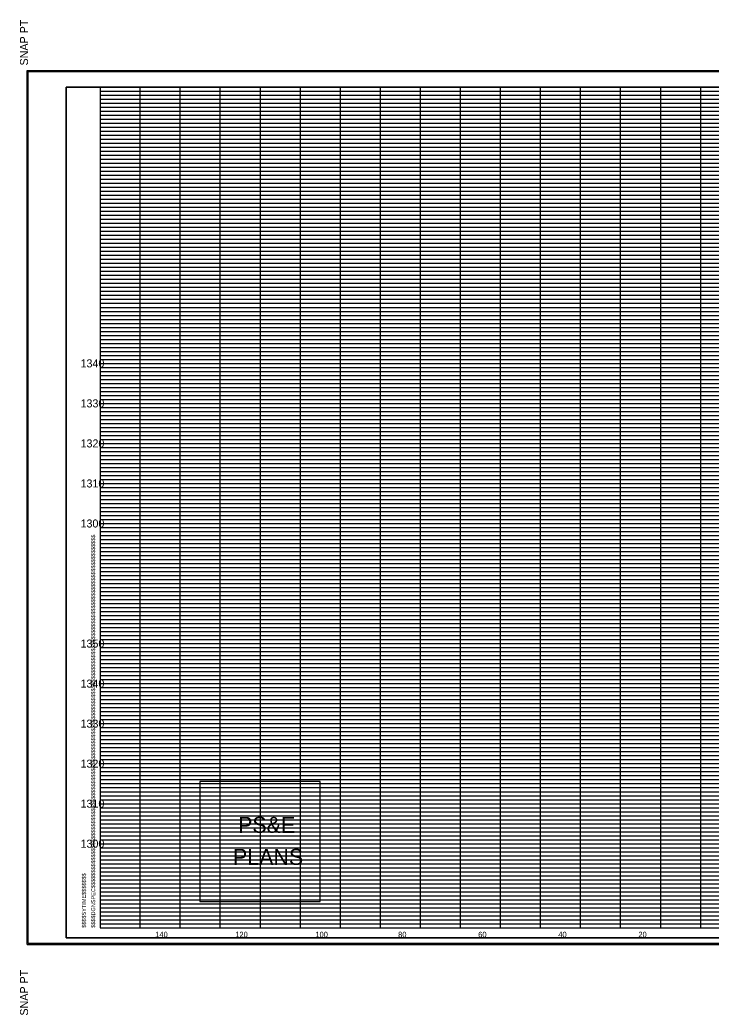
# Model space of a CAD drawing. Extents: x 980 to 1324, y 978 to 2847.
# Drawn here: x 979.9 to 1152.6, y 2328.2 to 2576.8 of the extents above; entities that cross this region are included whole.
import ezdxf

# ---------------------------------------------------------------- set-up
doc = ezdxf.new("R2010")
doc.units = 0
for name, color, linetype in [('DESIGN - SHEET - Corner Text', 7, 'Continuous'), ('DESIGN - SHEET - Light Grid', 7, 'Continuous'), ('DESIGN - SHEET - Linework', 7, 'Continuous'), ('DESIGN - SHEET - Plot Shape', 7, 'Continuous'), ('DESIGN - TYPICAL - Text', 7, 'Continuous')]:
    doc.layers.add(name, color=color, linetype=linetype)

# ---------------------------------------------------------------- blocks, each defined once
blk = doc.blocks.new('XSTSHT')
at = {"layer": 'DESIGN - SHEET - Light Grid'}
for p, q in [((0, 20.9), (8, 20.9)), ((8, 20.9), (16, 20.9)), ((0, 20.8), (8, 20.8)), ((0, 20.7), (8, 20.7)), ((8, 20.8), (16, 20.8)), ((8, 20.7), (16, 20.7)), ((0, 20.6), (8, 20.6)), ((0, 20.5), (8, 20.5)), ((0, 20.4), (8, 20.4)), ((8, 20.6), (16, 20.6)), ((8, 20.5), (16, 20.5)), ((8, 20.4), (16, 20.4)), ((0, 20.3), (8, 20.3)), ((0, 20.2), (8, 20.2)), ((8, 20.3), (16, 20.3)), ((8, 20.2), (16, 20.2)), ((0, 20.1), (8, 20.1)), ((0, 19.9), (8, 19.9)), ((8, 20.1), (16, 20.1)), ((8, 19.9), (16, 19.9)), ((0, 19.8), (8, 19.8)), ((0, 19.7), (8, 19.7)), ((8, 19.8), (16, 19.8)), ((8, 19.7), (16, 19.7)), ((0, 19.6), (8, 19.6)), ((0, 19.5), (8, 19.5)), ((0, 19.4), (8, 19.4)), ((8, 19.6), (16, 19.6)), ((8, 19.5), (16, 19.5)), ((8, 19.4), (16, 19.4)), ((0, 19.3), (8, 19.3)), ((0, 19.2), (8, 19.2)), ((8, 19.3), (16, 19.3)), ((8, 19.2), (16, 19.2)), ((0, 19.1), (8, 19.1)), ((0, 18.9), (8, 18.9)), ((8, 19.1), (16, 19.1)), ((8, 18.9), (16, 18.9)), ((0, 18.8), (8, 18.8)), ((0, 18.7), (8, 18.7)), ((8, 18.8), (16, 18.8)), ((8, 18.7), (16, 18.7)), ((0, 18.6), (8, 18.6)), ((0, 18.5), (8, 18.5)), ((0, 18.4), (8, 18.4)), ((8, 18.6), (16, 18.6)), ((8, 18.5), (16, 18.5)), ((8, 18.4), (16, 18.4)), ((0, 18.3), (8, 18.3)), ((0, 18.2), (8, 18.2)), ((8, 18.3), (16, 18.3)), ((8, 18.2), (16, 18.2)), ((0, 18.1), (8, 18.1)), ((8, 18.1), (16, 18.1)), ((0, 17.9), (8, 17.9)), ((0, 17.8), (8, 17.8)), ((0, 17.7), (8, 17.7)), ((8, 17.9), (16, 17.9)), ((8, 17.8), (16, 17.8)), ((8, 17.7), (16, 17.7)), ((0, 17.6), (8, 17.6)), ((0, 17.5), (8, 17.5)), ((8, 17.6), (16, 17.6)), ((8, 17.5), (16, 17.5)), ((0, 17.4), (8, 17.4)), ((0, 17.3), (8, 17.3)), ((0, 17.2), (8, 17.2)), ((8, 17.4), (16, 17.4)), ((8, 17.3), (16, 17.3)), ((8, 17.2), (16, 17.2)), ((0, 17.1), (8, 17.1)), ((8, 17.1), (16, 17.1)), ((0, 16.9), (8, 16.9)), ((0, 16.8), (8, 16.8)), ((0, 16.7), (8, 16.7)), ((8, 16.9), (16, 16.9)), ((8, 16.8), (16, 16.8)), ((8, 16.7), (16, 16.7)), ((0, 16.6), (8, 16.6)), ((0, 16.5), (8, 16.5)), ((8, 16.6), (16, 16.6)), ((8, 16.5), (16, 16.5)), ((0, 16.4), (8, 16.4)), ((0, 16.3), (8, 16.3)), ((0, 16.2), (8, 16.2)), ((8, 16.4), (16, 16.4)), ((8, 16.3), (16, 16.3)), ((8, 16.2), (16, 16.2)), ((0, 16.1), (8, 16.1)), ((8, 16.1), (16, 16.1)), ((0, 15.9), (8, 15.9)), ((0, 15.8), (8, 15.8)), ((0, 15.7), (8, 15.7)), ((8, 15.9), (16, 15.9)), ((8, 15.8), (16, 15.8)), ((8, 15.7), (16, 15.7)), ((0, 15.6), (8, 15.6)), ((0, 15.5), (8, 15.5)), ((8, 15.6), (16, 15.6)), ((8, 15.5), (16, 15.5)), ((0, 15.4), (8, 15.4)), ((0, 15.3), (8, 15.3)), ((0, 15.2), (8, 15.2)), ((8, 15.4), (16, 15.4)), ((8, 15.3), (16, 15.3)), ((8, 15.2), (16, 15.2)), ((0, 15.1), (8, 15.1)), ((8, 15.1), (16, 15.1)), ((0, 14.9), (8, 14.9)), ((0, 14.8), (8, 14.8)), ((0, 14.7), (8, 14.7)), ((8, 14.9), (16, 14.9)), ((8, 14.8), (16, 14.8)), ((8, 14.7), (16, 14.7)), ((0, 14.6), (8, 14.6)), ((0, 14.5), (8, 14.5)), ((8, 14.6), (16, 14.6)), ((8, 14.5), (16, 14.5)), ((0, 14.4), (8, 14.4)), ((0, 14.3), (8, 14.3)), ((0, 14.2), (8, 14.2)), ((8, 14.4), (16, 14.4)), ((8, 14.3), (16, 14.3)), ((8, 14.2), (16, 14.2)), ((0, 14.1), (8, 14.1)), ((8, 14.1), (16, 14.1)), ((0, 13.9), (8, 13.9)), ((0, 13.8), (8, 13.8)), ((0, 13.7), (8, 13.7)), ((8, 13.9), (16, 13.9)), ((8, 13.8), (16, 13.8)), ((8, 13.7), (16, 13.7)), ((0, 13.6), (8, 13.6)), ((0, 13.5), (8, 13.5)), ((8, 13.6), (16, 13.6)), ((8, 13.5), (16, 13.5)), ((0, 13.4), (8, 13.4)), ((0, 13.3), (8, 13.3)), ((0, 13.2), (8, 13.2)), ((8, 13.4), (16, 13.4)), ((8, 13.3), (16, 13.3)), ((8, 13.2), (16, 13.2)), ((0, 13.1), (8, 13.1)), ((8, 13.1), (16, 13.1)), ((0, 12.9), (8, 12.9)), ((0, 12.8), (8, 12.8)), ((0, 12.7), (8, 12.7)), ((8, 12.9), (16, 12.9)), ((8, 12.8), (16, 12.8)), ((8, 12.7), (16, 12.7)), ((0, 12.6), (8, 12.6)), ((0, 12.5), (8, 12.5)), ((8, 12.6), (16, 12.6)), ((8, 12.5), (16, 12.5)), ((0, 12.4), (8, 12.4)), ((0, 12.3), (8, 12.3)), ((0, 12.2), (8, 12.2)), ((8, 12.4), (16, 12.4)), ((8, 12.3), (16, 12.3)), ((8, 12.2), (16, 12.2)), ((0, 12.1), (8, 12.1)), ((8, 12.1), (16, 12.1)), ((0, 11.9), (8, 11.9)), ((0, 11.8), (8, 11.8)), ((0, 11.7), (8, 11.7)), ((8, 11.9), (16, 11.9)), ((8, 11.8), (16, 11.8)), ((8, 11.7), (16, 11.7)), ((0, 11.6), (8, 11.6)), ((0, 11.5), (8, 11.5)), ((8, 11.6), (16, 11.6)), ((8, 11.5), (16, 11.5)), ((0, 11.4), (8, 11.4)), ((0, 11.3), (8, 11.3)), ((0, 11.2), (8, 11.2)), ((8, 11.4), (16, 11.4)), ((8, 11.3), (16, 11.3)), ((8, 11.2), (16, 11.2)), ((0, 11.1), (8, 11.1)), ((8, 11.1), (16, 11.1)), ((0, 10.9), (8, 10.9)), ((0, 10.8), (8, 10.8)), ((0, 10.7), (8, 10.7)), ((8, 10.9), (16, 10.9)), ((8, 10.8), (16, 10.8)), ((8, 10.7), (16, 10.7)), ((0, 10.6), (8, 10.6)), ((0, 10.5), (8, 10.5)), ((8, 10.6), (16, 10.6)), ((8, 10.5), (16, 10.5)), ((0, 10.4), (8, 10.4)), ((0, 10.3), (8, 10.3)), ((0, 10.2), (8, 10.2)), ((8, 10.4), (16, 10.4)), ((8, 10.3), (16, 10.3)), ((8, 10.2), (16, 10.2)), ((0, 10.1), (8, 10.1)), ((8, 10.1), (16, 10.1)), ((0, 9.9), (8, 9.9)), ((0, 9.8), (8, 9.8)), ((0, 9.7), (8, 9.7)), ((8, 9.9), (16, 9.9)), ((8, 9.8), (16, 9.8)), ((8, 9.7), (16, 9.7)), ((0, 9.6), (8, 9.6)), ((0, 9.5), (8, 9.5)), ((8, 9.6), (16, 9.6)), ((8, 9.5), (16, 9.5)), ((0, 9.4), (8, 9.4)), ((0, 9.3), (8, 9.3)), ((0, 9.2), (8, 9.2)), ((8, 9.4), (16, 9.4)), ((8, 9.3), (16, 9.3)), ((8, 9.2), (16, 9.2)), ((0, 9.1), (8, 9.1)), ((8, 9.1), (16, 9.1)), ((0, 8.9), (8, 8.9)), ((0, 8.8), (8, 8.8)), ((8, 8.9), (16, 8.9)), ((8, 8.8), (16, 8.8)), ((0, 8.7), (8, 8.7)), ((0, 8.6), (8, 8.6)), ((0, 8.5), (8, 8.5)), ((8, 8.7), (16, 8.7)), ((8, 8.6), (16, 8.6)), ((8, 8.5), (16, 8.5)), ((0, 8.4), (8, 8.4)), ((0, 8.3), (8, 8.3)), ((8, 8.4), (16, 8.4)), ((8, 8.3), (16, 8.3)), ((0, 8.2), (8, 8.2)), ((0, 8.1), (8, 8.1)), ((8, 8.2), (16, 8.2)), ((8, 8.1), (16, 8.1)), ((0, 7.9), (8, 7.9)), ((0, 7.8), (8, 7.8)), ((8, 7.9), (16, 7.9)), ((8, 7.8), (16, 7.8)), ((0, 7.7), (8, 7.7)), ((0, 7.6), (8, 7.6)), ((0, 7.5), (8, 7.5)), ((8, 7.7), (16, 7.7)), ((8, 7.6), (16, 7.6)), ((8, 7.5), (16, 7.5)), ((0, 7.4), (8, 7.4)), ((0, 7.3), (8, 7.3)), ((8, 7.4), (16, 7.4)), ((8, 7.3), (16, 7.3)), ((0, 7.2), (8, 7.2)), ((0, 7.1), (8, 7.1)), ((8, 7.2), (16, 7.2)), ((8, 7.1), (16, 7.1)), ((0, 6.9), (8, 6.9)), ((0, 6.8), (8, 6.8)), ((8, 6.9), (16, 6.9)), ((8, 6.8), (16, 6.8)), ((0, 6.7), (8, 6.7)), ((0, 6.6), (8, 6.6)), ((0, 6.5), (8, 6.5)), ((8, 6.7), (16, 6.7)), ((8, 6.6), (16, 6.6)), ((8, 6.5), (16, 6.5)), ((0, 6.4), (8, 6.4)), ((0, 6.3), (8, 6.3)), ((8, 6.4), (16, 6.4)), ((8, 6.3), (16, 6.3)), ((0, 6.2), (8, 6.2)), ((0, 6.1), (8, 6.1)), ((8, 6.2), (16, 6.2)), ((8, 6.1), (16, 6.1)), ((0, 5.9), (8, 5.9)), ((0, 5.8), (8, 5.8)), ((8, 5.9), (16, 5.9)), ((8, 5.8), (16, 5.8)), ((0, 5.7), (8, 5.7)), ((0, 5.6), (8, 5.6)), ((0, 5.5), (8, 5.5)), ((8, 5.7), (16, 5.7)), ((8, 5.6), (16, 5.6)), ((8, 5.5), (16, 5.5)), ((0, 5.4), (8, 5.4)), ((0, 5.3), (8, 5.3)), ((8, 5.4), (16, 5.4)), ((8, 5.3), (16, 5.3)), ((0, 5.2), (8, 5.2)), ((0, 5.1), (8, 5.1)), ((8, 5.2), (16, 5.2)), ((8, 5.1), (16, 5.1)), ((0, 4.9), (8, 4.9)), ((0, 4.8), (8, 4.8)), ((8, 4.9), (16, 4.9)), ((8, 4.8), (16, 4.8)), ((0, 4.7), (8, 4.7)), ((0, 4.6), (8, 4.6)), ((0, 4.5), (8, 4.5)), ((8, 4.7), (16, 4.7)), ((8, 4.6), (16, 4.6)), ((8, 4.5), (16, 4.5)), ((0, 4.4), (8, 4.4)), ((0, 4.3), (8, 4.3)), ((8, 4.4), (16, 4.4)), ((8, 4.3), (16, 4.3)), ((0, 4.2), (8, 4.2)), ((0, 4.1), (8, 4.1)), ((8, 4.2), (16, 4.2)), ((8, 4.1), (16, 4.1)), ((0, 3.9), (8, 3.9)), ((0, 3.8), (8, 3.8)), ((8, 3.9), (16, 3.9)), ((8, 3.8), (16, 3.8)), ((0, 3.7), (8, 3.7)), ((0, 3.6), (8, 3.6)), ((0, 3.5), (8, 3.5)), ((8, 3.7), (16, 3.7)), ((8, 3.6), (16, 3.6)), ((8, 3.5), (16, 3.5)), ((0, 3.4), (8, 3.4)), ((0, 3.3), (8, 3.3)), ((8, 3.4), (16, 3.4)), ((8, 3.3), (16, 3.3)), ((0, 3.2), (8, 3.2)), ((0, 3.1), (8, 3.1)), ((8, 3.2), (16, 3.2)), ((8, 3.1), (16, 3.1)), ((0, 2.9), (8, 2.9)), ((0, 2.8), (8, 2.8)), ((8, 2.9), (16, 2.9)), ((8, 2.8), (16, 2.8)), ((0, 2.7), (8, 2.7)), ((0, 2.6), (8, 2.6)), ((0, 2.5), (8, 2.5)), ((8, 2.7), (16, 2.7)), ((8, 2.6), (16, 2.6)), ((8, 2.5), (16, 2.5)), ((0, 2.4), (8, 2.4)), ((0, 2.3), (8, 2.3)), ((8, 2.4), (16, 2.4)), ((8, 2.3), (16, 2.3)), ((0, 2.2), (8, 2.2)), ((0, 2.1), (8, 2.1)), ((8, 2.2), (16, 2.2)), ((8, 2.1), (16, 2.1)), ((0, 1.9), (8, 1.9)), ((0, 1.8), (8, 1.8)), ((8, 1.9), (16, 1.9)), ((8, 1.8), (16, 1.8)), ((0, 1.7), (8, 1.7)), ((0, 1.6), (8, 1.6)), ((0, 1.5), (8, 1.5)), ((8, 1.7), (16, 1.7)), ((8, 1.6), (16, 1.6)), ((8, 1.5), (16, 1.5)), ((0, 1.4), (8, 1.4)), ((0, 1.3), (8, 1.3)), ((8, 1.4), (16, 1.4)), ((8, 1.3), (16, 1.3)), ((0, 1.2), (8, 1.2)), ((0, 1.1), (8, 1.1)), ((8, 1.2), (16, 1.2)), ((8, 1.1), (16, 1.1)), ((0, 0.9), (8, 0.9)), ((0, 0.8), (8, 0.8)), ((8, 0.9), (16, 0.9)), ((8, 0.8), (16, 0.8)), ((0, 0.7), (8, 0.7)), ((0, 0.6), (8, 0.6)), ((0, 0.5), (8, 0.5)), ((8, 0.7), (16, 0.7)), ((8, 0.6), (16, 0.6)), ((8, 0.5), (16, 0.5)), ((0, 0.4), (8, 0.4)), ((0, 0.3), (8, 0.3)), ((8, 0.4), (16, 0.4)), ((8, 0.3), (16, 0.3)), ((0, 0.2), (8, 0.2)), ((0, 0.1), (8, 0.1)), ((8, 0.2), (16, 0.2)), ((8, 0.1), (16, 0.1))]:
    blk.add_line(p, q, dxfattribs=at)
at = {"layer": 'DESIGN - SHEET - Linework'}
for p, q in [((-1.823, -0.414), (-1.823, 21.414)), ((-1.823, 21.414), (32.217, 21.414)), ((1, 0), (1, 21)), ((2, 0), (2, 21)), ((3, 0), (3, 21)), ((4, 0), (4, 21)), ((5, 0), (5, 21)), ((6, 0), (6, 21)), ((7, 0), (7, 21)), ((8, 0), (8, 21)), ((9, 0), (9, 21)), ((10, 0), (10, 21)), ((11, 0), (11, 21)), ((12, 0), (12, 21)), ((13, 0), (13, 21)), ((14, 0), (14, 21)), ((15, 0), (15, 21)), ((0, 20), (28, 20)), ((0, 19), (32, 19)), ((0, 18), (32, 18)), ((0, 17), (32, 17)), ((0, 16), (32, 16)), ((0, 15), (32, 15)), ((0, 14), (32, 14)), ((0, 13), (32, 13)), ((0, 12), (32, 12)), ((0, 11), (32, 11)), ((0, 10), (32, 10)), ((0, 9), (32, 9)), ((0, 8), (32, 8)), ((0, 7), (32, 7)), ((0, 6), (32, 6)), ((0, 5), (32, 5)), ((0, 4), (32, 4)), ((0, 3), (32, 3)), ((0, 2), (32, 2)), ((0, 1), (32, 1)), ((-1.823, -0.414), (32.217, -0.414))]:
    blk.add_line(p, q, dxfattribs=at)
blk.add_lwpolyline([(0, 21), (0, 0), (32, 0), (32, 21), (0, 21)], dxfattribs=at)
at = {"layer": 'DESIGN - SHEET - Plot Shape'}
for points in [[(-1.803, 21.394), (32.197, 21.394), (32.197, -0.394), (-1.803, -0.394)], [(-0.85, 21), (32, 21), (32, -0.25), (-0.85, -0.25)]]:
    blk.add_lwpolyline(points, close=True, dxfattribs=at)
at = {"layer": 'DESIGN - SHEET - Corner Text'}
for s, height, p in [('  SNAP PT', 0.2, (-1.803, 21.394)), ('$$$$DGNSPEC$$$$$$$$$$$$$$$$$$$$$$$$$$$$$$$$$$$$$$$$$$$$$$$$$$$$$$$$$$$$$$$$$$$$$$$$$$$$$$$$$$$$$$$$$$$$$$$$$$$$$$$$$$$$$$$$$$$', 0.100002, (-0.126, 0)), ('$$$$SYTIME$$$$$$$', 0.1, (-0.358, 0)), ('SNAP PT  ', 0.2, (-1.803, -2.194))]:
    blk.add_text(s, height=height, rotation=90, dxfattribs=at).set_placement(p)

msp = doc.modelspace()

# ---------------------------------------------------------------- linework, layer by layer
at = {"layer": 'DESIGN - SHEET - Corner Text'}
msp.add_lwpolyline([(1024.92, 2386.54), (1024.92, 2356.54), (1054.92, 2356.54), (1054.92, 2386.54)], close=True, dxfattribs=at)
at = {"layer": 'DESIGN - SHEET - Plot Shape'}
msp.add_lwpolyline([(991.5, 2347.5), (1320, 2347.5), (1320, 2560), (991.5, 2560)], close=True, dxfattribs=at)

# ---------------------------------------------------------------- block references
at = {"layer": 'DESIGN - SHEET - Plot Shape', "xscale": 10, "yscale": 10}
msp.add_blockref('XSTSHT', (1000, 2350), dxfattribs=at)

# ---------------------------------------------------------------- texts
at = {"layer": 'DESIGN - SHEET - Corner Text'}
for s, p in [('PS&E', (1034.44, 2373.71)), ('PLANS', (1033.16, 2365.71))]:
    msp.add_text(s, height=4, dxfattribs=at).set_placement(p)
at = {"layer": 'DESIGN - TYPICAL - Text'}
for s, height, p in [('     1340     ', 2, (991.37, 2490)), ('     1330     ', 2, (991.37, 2480)), ('     1320     ', 2, (991.37, 2470)), ('     1310     ', 2, (991.37, 2460)), ('     1300     ', 2, (991.37, 2450)), ('     1350     ', 2, (991.37, 2420)), ('     1340     ', 2, (991.37, 2410)), ('     1330     ', 2, (991.37, 2400)), ('     1320     ', 2, (991.37, 2390)), ('     1310     ', 2, (991.37, 2380)), ('     1300     ', 2, (991.37, 2370)), ('     140     ', 1.4, (1011.14, 2347.6)), ('     120     ', 1.4, (1031.14, 2347.6)), ('     100     ', 1.4, (1051.14, 2347.6)), ('     80     ', 1.4, (1071.82, 2347.6)), ('     60     ', 1.4, (1091.82, 2347.6)), ('     40     ', 1.4, (1111.82, 2347.6)), ('     20     ', 1.4, (1131.82, 2347.6))]:
    msp.add_text(s, height=height, dxfattribs=at).set_placement(p)

doc.saveas('drawing.dxf')
